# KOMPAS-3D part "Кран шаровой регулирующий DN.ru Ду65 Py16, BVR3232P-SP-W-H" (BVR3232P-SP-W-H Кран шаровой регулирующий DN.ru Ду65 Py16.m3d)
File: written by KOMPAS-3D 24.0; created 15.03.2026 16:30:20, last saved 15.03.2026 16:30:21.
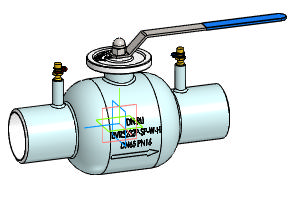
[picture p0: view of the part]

Document properties: Автор: Максим; Полное имя файла: D:\Rabota ebanaya\BVR3232P-SP-W-H Кран шаровой регулирующий Ду15-150\Типоразмеры\DN65\BVR3232P-SP-W-H Кран шаровой регулирующий DN.ru Ду65 Py16.m3d

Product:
- Body: Тело 1  | qty 1
    Масса: 13.796902
- Part/product: Кран шаровой регулирующий DN.ru Ду65 Py16  | designation BVR3232P-SP-W-H
    Масса: 6.3
    Раздел спецификации: Прочие изделия
    Примечание: D160-69412

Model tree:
1. Операция без истории:1

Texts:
  BVR3232P-SP-W-H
